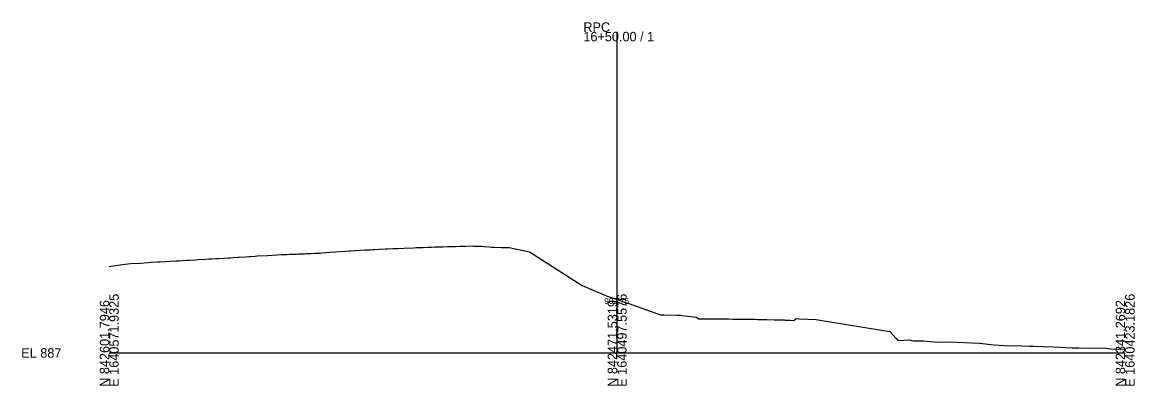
# Model space of a CAD drawing. Extents: x -26 to 1640245, y -10 to 842531.
# Drawn here: x 1274.3 to 1602.8, y 2490.3 to 2597.7 of the extents above; entities that cross this region are included whole.
import ezdxf

# ---------------------------------------------------------------- set-up
doc = ezdxf.new("R2010")
doc.units = 0
for name, color, linetype in [('Exist Cross Section Cell', 7, 'Continuous'), ('Exist XS Center Line Elevation Label', 7, 'Continuous'), ('Exist XS Ground Line', 7, 'Continuous')]:
    doc.layers.add(name, color=color, linetype=linetype)

msp = doc.modelspace()

# ---------------------------------------------------------------- linework, layer by layer
at = {"layer": 'Exist Cross Section Cell'}
for p, q in [((1450, 2500), (1450, 2594.84)), ((1300, 2500), (1450, 2500)), ((1450, 2500), (1600, 2500))]:
    msp.add_line(p, q, dxfattribs=at)
at = {"layer": 'Exist XS Ground Line'}
msp.add_lwpolyline([(1300, 2525.53), (1300.6, 2525.62), (1304.6, 2526.24), (1306.42, 2526.39), (1309.26, 2526.53), (1311.46, 2526.71), (1312.38, 2526.78), (1314.15, 2526.88), (1315.02, 2526.93), (1316.5, 2527.02), (1317.9, 2527.1), (1319.76, 2527.19), (1320.78, 2527.25), (1321.54, 2527.28), (1322.89, 2527.36), (1323.66, 2527.41), (1325.47, 2527.52), (1326.45, 2527.58), (1328.39, 2527.7), (1329.42, 2527.75), (1330.22, 2527.8), (1331.63, 2527.89), (1332.29, 2527.93), (1333.88, 2528.02), (1335.17, 2528.08), (1335.72, 2528.11), (1336.67, 2528.16), (1337.96, 2528.24), (1338.4, 2528.28), (1340.26, 2528.4), (1341.21, 2528.47), (1341.71, 2528.5), (1343.05, 2528.59), (1343.81, 2528.64), (1346.75, 2528.81), (1349.57, 2528.98), (1350.72, 2529.03), (1351.17, 2529.05), (1351.79, 2529.08), (1352.45, 2529.1), (1353.31, 2529.13), (1355.32, 2529.21), (1355.87, 2529.23), (1356.84, 2529.27), (1357.71, 2529.31), (1358.2, 2529.33), (1359.16, 2529.36), (1359.67, 2529.38), (1360.7, 2529.43), (1362.31, 2529.51), (1362.82, 2529.55), (1363.96, 2529.66), (1365.04, 2529.73), (1366.92, 2529.86), (1369.72, 2530.07), (1370.74, 2530.15), (1371.19, 2530.18), (1372.6, 2530.27), (1374.2, 2530.36), (1375.48, 2530.43), (1377.01, 2530.5), (1377.86, 2530.54), (1378.35, 2530.57), (1379.7, 2530.63), (1381.53, 2530.72), (1382.05, 2530.75), (1383.87, 2530.84), (1384.24, 2530.86), (1385.19, 2530.89), (1387.09, 2530.97), (1389.87, 2531.08), (1390.69, 2531.11), (1392.13, 2531.16), (1392.75, 2531.19), (1394.19, 2531.25), (1395.13, 2531.28), (1396.19, 2531.31), (1397.17, 2531.34), (1398.02, 2531.36), (1398.51, 2531.37), (1399.85, 2531.41), (1401.39, 2531.45), (1401.69, 2531.46), (1402.22, 2531.47), (1403.52, 2531.51), (1404.26, 2531.54), (1405.35, 2531.58), (1407.16, 2531.59), (1407.65, 2531.58), (1410.02, 2531.55), (1410.85, 2531.48), (1412.3, 2531.34), (1412.9, 2531.29), (1413.7, 2531.25), (1415.78, 2531.16), (1416.98, 2531.12), (1418.1, 2531.1), (1424.08, 2529.85), (1439.69, 2519.89), (1446.19, 2517.13), (1447.02, 2516.77), (1450, 2515.75), (1453.48, 2514.57), (1461.45, 2511.7), (1462.92, 2511.24), (1463.92, 2511.24), (1467.7, 2511.17), (1468.48, 2511.15), (1468.79, 2511.11), (1469.13, 2511.07), (1473.45, 2510.6), (1474.05, 2510.08), (1475.59, 2510.08), (1475.9, 2510.08), (1477.85, 2510.08), (1479.11, 2510.07), (1480.49, 2510.07), (1481.99, 2510.05), (1482.89, 2510.04), (1484.15, 2510.02), (1484.87, 2510.01), (1487.83, 2509.99), (1488.25, 2509.98), (1489.36, 2509.95), (1490.63, 2509.93), (1491.48, 2509.92), (1492.97, 2509.89), (1493.51, 2509.88), (1494.22, 2509.87), (1496.39, 2509.81), (1496.98, 2509.8), (1498.02, 2509.77), (1498.81, 2509.75), (1499.26, 2509.74), (1499.59, 2509.72), (1500.42, 2509.68), (1501.04, 2509.66), (1502.21, 2509.6), (1502.88, 2510.16), (1503.83, 2510.11), (1508.8, 2509.85), (1512.86, 2509.19), (1530.53, 2506.36), (1532.4, 2504.3), (1532.73, 2503.79), (1533.44, 2503.68), (1534.63, 2503.79), (1536.3, 2503.86), (1537.43, 2503.53), (1540.45, 2503.53), (1544.59, 2503.2), (1548.03, 2503.3), (1556.98, 2502.9), (1561.35, 2502.39), (1564.31, 2502.18), (1569.49, 2502.07), (1571.64, 2502.03), (1572.87, 2501.98), (1578.97, 2501.85), (1584.38, 2501.55), (1586.3, 2501.5), (1589.66, 2501.4), (1593.63, 2501.46), (1595.9, 2501.26), (1600, 2501.11)], dxfattribs=at)

# ---------------------------------------------------------------- texts
at = {"layer": 'Exist Cross Section Cell'}
for s, p in [('RPC', (1440, 2594.84)), ('16+50.00 / 1', (1440, 2592.04)), ('EL 887', (1274, 2498.6))]:
    msp.add_text(s, height=2.8, dxfattribs=at).set_placement(p)
for s, p in [('E 1640571.9325', (1302.8, 2490)), ('E 1640497.5576', (1452.8, 2490)), ('E 1640423.1826', (1602.8, 2490)), ('N 842601.7946', (1300, 2490)), ('N 842471.5319', (1450, 2490)), ('N 842341.2692', (1600, 2490))]:
    msp.add_text(s, height=2.8, rotation=90, dxfattribs=at).set_placement(p)
at = {"layer": 'Exist XS Center Line Elevation Label'}
msp.add_text('902.75', height=1.8, dxfattribs=at).set_placement((1446.17, 2514.45))

doc.saveas('drawing.dxf')
